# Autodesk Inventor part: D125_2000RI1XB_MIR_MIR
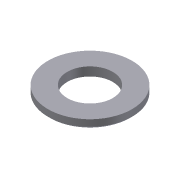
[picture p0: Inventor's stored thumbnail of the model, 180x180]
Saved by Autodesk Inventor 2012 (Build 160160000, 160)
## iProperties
Company: CAD-Verlag
Shininess: 64.0
Length Units: 11269
Angle Units: 11279
Time Units: 11290
Mass Units: 11283
Length Display Precision: 3
Angle Display Precision: 2
Compacted: True
Part Number: D125_2000RI1XB_MIR_MIR
Document SubType Name: Modeling
Created: 2004-09
Material: Steel, Mild
Designer: Greiling
Manufacturer: Standard
Standards Organization: Custom
Density: 1 g/cm^3
Density: 0.0
Volumn: 0.0
Area: 0.0
PropertySet Name: Model Information
Control State: 0
Master: False
Checked Out: False
Author: Jürgen Kronas
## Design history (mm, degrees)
derived "D125_2000RI1XB_MIR.ipt" dims "d16" = 0
  node "WorkPlane1"
  node "WorkPlane3"
  node "MSC_PT1"
  node "MSC_PT2"
  node "WorkAxis1"
  node "MSC_A1"
  node "WorkPoint2"
  node "WorkPoint1"
node "Volumenkörper1"
node "Volumenkörpern"
node "Oberflächenkörpern"
tag "Bezeichnung2"
feature "Volumenkörper1::D125_2000RI1XB_MIR.ipt" dims "d0" = 10, "d16" = 0
